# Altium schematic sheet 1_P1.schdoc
size 307 x 218 mm; Symbol: Drawing-Symbol_A4; Device: Drawing-Symbol_A4; @Project Name: ESP32 Drone; @Page Count: 2; @Update Date: 2026-03-31; @Create Date: 2025-12-19; @Schematic Name: Schematic1; @Page No: 1; @Page Name: P1; Company: Sprig Labs; Version: V1.0; Page Size: A4; Drawn: K. Paraskevas; @Create Time: 19:21:42; @Update Time: 17:37:33; Width: 1170; Height: 825; Region Start: 1; X Region Count: 6; Y Region Count: 4; Blade Width: 10; Title Block Position: 3; @Board Name: Board1
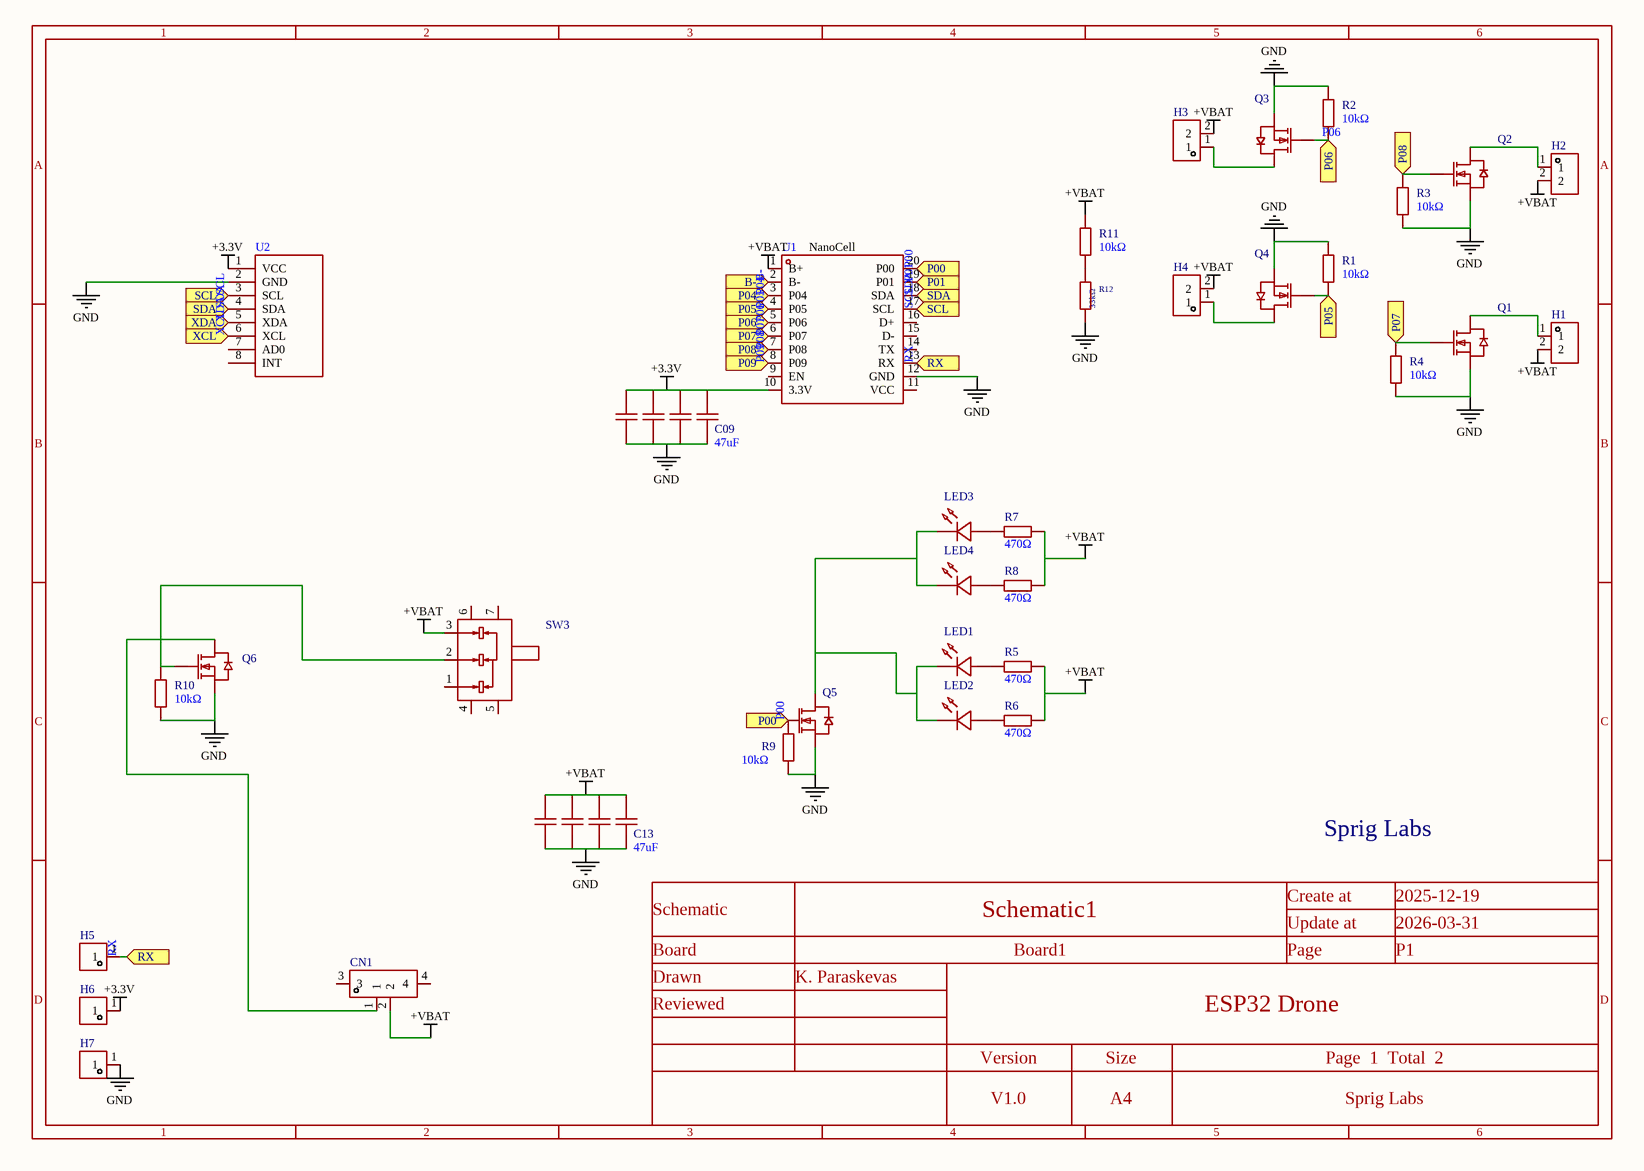
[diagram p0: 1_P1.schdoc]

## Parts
C09  47uF  [C0805]
C10  47uF  [C0805]  (value not drawn)
C11  47uF  [C0805]  (value not drawn)
C12  47uF  [C0805]  (value not drawn)
C13  47uF  [C0805]
C14  47uF  [C0805]  (value not drawn)
C15  47uF  [C0805]  (value not drawn)
C16  47uF  [C0805]  (value not drawn)
CN1  HX PH2.0-2PWT  [CONN-SMD_2P-P2.00]  (value not drawn)
H1  KF332J-3.5-2P BLACK  [HDR-TH_2P-P3.50-V-M_1]  (value not drawn)
H2  KF332J-3.5-2P BLACK  [HDR-TH_2P-P3.50-V-M_1]  (value not drawn)
H3  KF332J-3.5-2P BLACK  [HDR-TH_2P-P3.50-V-M_1]  (value not drawn)
H4  KF332J-3.5-2P BLACK  [HDR-TH_2P-P3.50-V-M_1]  (value not drawn)
H5  TMM-101-01-G-S  [HDR-TH_TMM-101-06-L-S]  (value not drawn)
H6  TMM-101-01-G-S  [HDR-TH_TMM-101-06-L-S]  (value not drawn)
H7  TMM-101-01-G-S  [HDR-TH_TMM-101-06-L-S]  (value not drawn)
LED1  XL-1608SURC-06  [LED0603-RD_RED]  (value not drawn)
LED2  XL-1608SURC-06  [LED0603-RD_RED]  (value not drawn)
LED3  PSC-1608U50GC-G4  [LED0603-RD_GREEN]  (value not drawn)
LED4  PSC-1608U50GC-G4  [LED0603-RD_GREEN]  (value not drawn)
Q1  100N03A  [TO-252-2_L6.6-W6.1-P4.57-LS9.9-BR-CW]  (value not drawn)
Q2  100N03A  [TO-252-2_L6.6-W6.1-P4.57-LS9.9-BR-CW]  (value not drawn)
Q3  100N03A  [TO-252-2_L6.6-W6.1-P4.57-LS9.9-BR-CW]  (value not drawn)
Q4  100N03A  [TO-252-2_L6.6-W6.1-P4.57-LS9.9-BR-CW]  (value not drawn)
Q5  SI2302-HXY  [SOT-23-3_L2.9-W1.3-P1.90-LS2.4-BR]  (value not drawn)
Q6  100N03A  [TO-252-2_L6.6-W6.1-P4.57-LS9.9-BR-CW]  (value not drawn)
R1  10kΩ  [R0603]
R2  10kΩ  [R0603]
R3  10kΩ  [R0603]
R4  10kΩ  [R0603]
R5  470Ω  [R0603]
R6  470Ω  [R0603]
R7  470Ω  [R0603]
R8  470Ω  [R0603]
R9  10kΩ  [R0603]
R10  10kΩ  [R0603]
R11  10kΩ  [R0603]
R12  33kΩ  [R0603]
SW3  MK-12C03-G015  [SW-SMD_MK-12C03-G015]  (value not drawn)
U1  (no value)  [NanoCell]
U2  (no value)  [MPU-6050 module]

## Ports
B- (in), P00 (in), P01 (in), P04 (in), P05 (in), P06 (in), P07 (in), P08 (in), P09 (in), RX (in), SCL (in), SDA (in), XCL (in), XDA (in)

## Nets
+3.3V: C09.2 C10.2 C11.2 C12.2 H6.1 U1.10(3.3V) U2.1(VCC)
+VBAT: C13.2 C14.2 C15.2 C16.2 CN1.2 H1.2 H2.2 H3.2 H4.2 R5.2 R6.2 R7.2 R8.2 R11.2 SW3.3 U1.1(B+)
GND: C09.1 C10.1 C11.1 C12.1 C13.1 C14.1 C15.1 C16.1 H7.1 Q1.3(S) Q2.3(S) Q3.3(S) Q4.3(S) Q5.2(S) Q6.3(S) R1.2 R2.2 R3.2 R4.2 R9.2 R10.2 R12.1 U1.12(GND) U2.2(GND)
B-: U1.2(B-) ; port B-
P00: Q5.1(G) R9.1 U1.20(P00) ; port P00
P01: U1.19(P01) ; port P01
P04: U1.3(P04) ; port P04
P05: Q4.1(G) R1.1 U1.4(P05) ; port P05
P06: Q3.1(G) R2.1 U1.5(P06) ; port P06
P07: Q1.1(G) R4.1 U1.6(P07) ; port P07
P08: Q2.1(G) R3.1 U1.7(P08) ; port P08
P09: U1.8(P09) ; port P09
RX: H5.1 U1.13(RX) ; port RX
SCL: U1.17(SCL) U2.3(SCL) ; port SCL
SDA: U1.18(SDA) U2.4(SDA) ; port SDA
XCL: U2.6(XCL) ; port XCL
XDA: U2.5(XDA) ; port XDA
NetCN1_1: CN1.1 Q6.2(D)
NetH1_1: H1.1 Q1.2(D)
NetH2_1: H2.1 Q2.2(D)
NetH3_1: H3.1 Q3.2(D)
NetH4_1: H4.1 Q4.2(D)
NetLED1_1: LED1.1(K) LED2.1(K) LED3.1(K) LED4.1(K) Q5.3(D)
NetLED1_2: LED1.2(A) R5.1
NetLED2_2: LED2.2(A) R6.1
NetLED3_2: LED3.2(A) R7.1
NetLED4_2: LED4.2(A) R8.1
NetQ6_1: Q6.1(G) R10.1 SW3.2
NetR11_1: R11.1 R12.2

Not connected (* = marked no-connect by the designer): CN1 3 4; SW3 1 4 5 6 7; U1 9(EN) 11(VCC) 14(TX) 15(D-) 16(D+); U2 7(AD0) 8(INT)

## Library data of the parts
C09-C16 = JMK212BJ476MG-T: Manufacturer: TAIYO YUDEN(太诱); Symbol: TCC0603X5R226M6R3CT; Add into BOM: yes; Tolerance: ±20%; Voltage Rating: 6.3V; Temperature Coefficient: X5R
CN1 = HX PH2.0-2PWT: Manufacturer: hanxia(韩下); Add into BOM: yes; Pins Structure: 1x2P; Pitch: 2mm; Reference Series: PH; Number of PINs Per Row: 2; Current Rating: 2A; Voltage Rating: 100V; Plastic Material: LCP; Flame Retardant Rating: UL94V-0
H1-H4 = KF332J-3.5-2P BLACK: Manufacturer: KEFA(科发); Symbol: TMM-102-03-L-S; Add into BOM: yes; Pin Structure: 1x2P; Pitch: 3.5mm; Circluar Pins/Square Pins: Round Pin
H5-H7 = TMM-101-01-G-S: Manufacturer: SAMTEC; Add into BOM: yes; Current Rating: 3.2A
LED1 LED2 = XL-1608SURC-06: Manufacturer: XINGLIGHT(成兴光); Add into BOM: yes; Illumination Color: Red; Voltage - Forward(Vf): 2.3V; Power(Watts): 50mW; Forward Current: 20mA; Wavelength - Dominant: 620nm~630nm; Peak Wavelength: 625nm; Lens Color: Water Clear; Luminous Intensity: 225mcd; Viewing Angle: 120°
LED3 LED4 = PSC-1608U50GC-G4: Manufacturer: HONGLITRONIC(鸿利光电); Add into BOM: yes; Illumination Color: Green; Voltage - Forward(Vf): 3.2V; Power(Watts): 66mW; Forward Current: 10mA; Wavelength - Dominant: 517nm~527nm; Lens Color: Water Clear; Luminous Intensity: 1000mcd; Viewing Angle: 130°
Q1-Q4 Q6 = 100N03A: Manufacturer: UMW(友台半导体); Add into BOM: yes; Number: 1 N-Channel; Drain to Source Voltage: 30V; Current - Continuous Drain(Id): 90A; RDS(on): 3.8mΩ@10V；6.4mΩ@4.5V; Pd - Power Dissipation: 105W; Gate Threshold Voltage (Vgs(th)): 1.7V@250uA; Gate Charge(Qg): 41nC@10V; Input Capacitance(Ciss): 1.963nF@15V; Reverse Transfer Capacitance (Crss@Vds): 221pF; Type: N-Channel
Q5 = SI2302-HXY: Manufacturer: HXY MOSFET(华轩阳电子); Symbol: SI2302_C4748714; Add into BOM: yes; Type: 1 N-channel; Drain Source On Resistance (RDS(on)@Vgs,Id): 55mΩ@4.5V,2.8A; Power Dissipation (Pd): 900mW; Gate Threshold Voltage (Vgs(th)@Id): 1.2V@250uA; Total Gate Charge (Qg@Vgs): 5nC@4.5V; Input Capacitance (Ciss@Vds): 260pF; Reverse Transfer Capacitance (Crss@Vds): 27pF
R1-R4 R9 R10 = 0603WAF1002T5E: Manufacturer: UNI-ROYAL(厚声); Symbol: 0603WAF1003T5E; Add into BOM: yes; Tolerance: ±1%; Power(Watts): 100mW; Voltage-Supply(Max): 75V; Temperature Coefficient: ±100ppm/℃
R5-R8 = 0603WAF4700T5E: Manufacturer: UNI-ROYAL(厚声); Add into BOM: yes; Tolerance: ±1%; Power(Watts): 100mW; Voltage-Supply(Max): 75V; Temperature Coefficient: ±100ppm/℃
R11 = 0603WAF1002T5E: Manufacturer: UNI-ROYAL(厚声); Symbol: 0603WAF1003T5E; Add into BOM: no; Tolerance: ±1%; Power(Watts): 100mW; Voltage-Supply(Max): 75V; Temperature Coefficient: ±100ppm/℃
R12 = 0603WAF3302T5E: Manufacturer: UNI-ROYAL(厚声); Add into BOM: no; Tolerance: ±1%; Power(Watts): 100mW; Voltage-Supply(Max): 75V; Temperature Coefficient: ±100ppm/℃
SW3 = MK-12C03-G015: Manufacturer: G-Switch(品赞); Add into BOM: yes; Circuit: SPDT; Actuator Style: Rectangular columnar; Pin Style: SMDSplicing; Switch Length: 6.65mm; Switch Width: 2.75mm; Switch Height: 4.25mm; Actuator Color: White; Current Rating (DC): 1A; Voltage Rating (DC): 6V; Mechanical Life: 1万次
U1 = NanoCell: Add into BOM: yes
U2 = MPU-6050 module: Add into BOM: yes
